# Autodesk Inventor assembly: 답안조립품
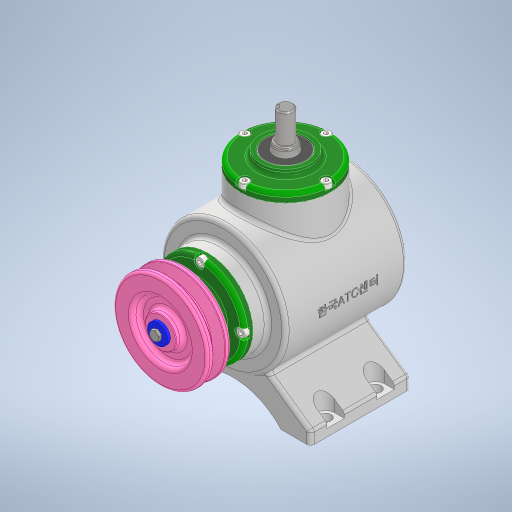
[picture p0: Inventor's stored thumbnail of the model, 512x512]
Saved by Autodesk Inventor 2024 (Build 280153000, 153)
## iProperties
Created: 2023-08
Part Number: 답안조립품
Document SubType Name: Assembly
Designer: Owner
Author: Owner
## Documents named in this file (17)
- C:\Users\Owner\Desktop\730813V1013\답안조립품.iam
- C:\Users\Owner\Desktop\730813V1013\본체.ipt
- C:\Users\Owner\Desktop\730813V1013\V-벨트풀리.ipt
- C:\Users\Owner\Desktop\730813V1013\메인 베벨기어.ipt
- C:\Users\Owner\Desktop\730813V1013\메인 축.ipt
- 메인 축.ipt
- C:\Users\Owner\Desktop\730813V1013\베어링 6203.ipt
- C:\Users\Owner\Desktop\730813V1013\볼트 M4 x 10.ipt
- C:\Users\Owner\Desktop\730813V1013\서브 베벨기어.ipt
- C:\Users\Owner\Desktop\730813V1013\서브 축.ipt
- 서브 축.ipt
- C:\Users\Owner\Desktop\730813V1013\오일실 17 x 32 x 8.ipt
- C:\Users\Owner\Desktop\730813V1013\와셔 4 x 16.ipt
- C:\Users\Owner\Desktop\730813V1013\육각볼트 M4 x 8.ipt
- C:\Users\Owner\Desktop\730813V1013\커버.ipt
- C:\Users\Owner\Desktop\730813V1013\키 4 x 4 x 14.ipt
- C:\Users\Owner\Desktop\730813V1013\키 5 x 5 x 14.ipt
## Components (1 placed, 1 different names)
1. V-벨트풀리:1
